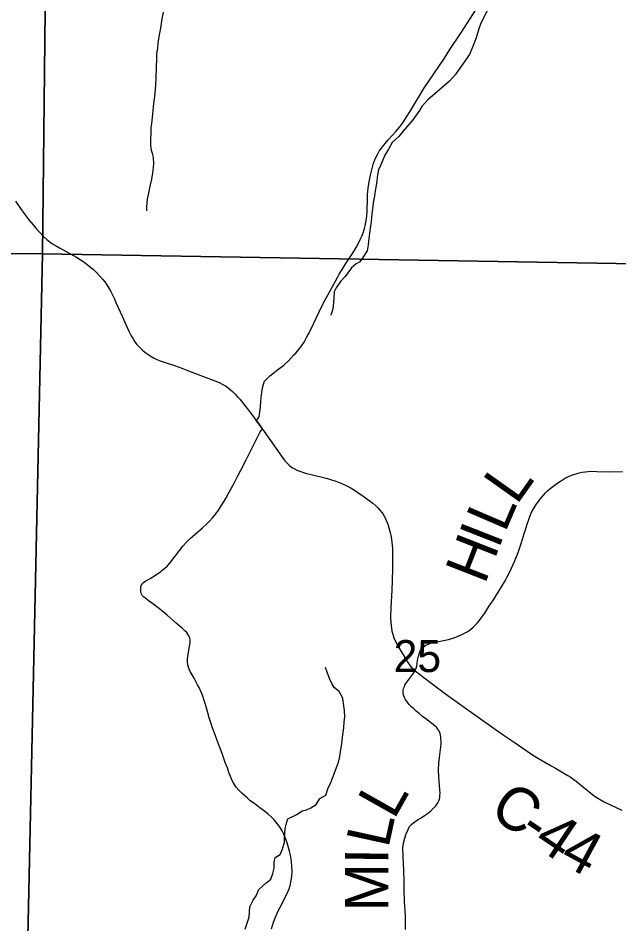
# Model space of a CAD drawing. Extents: x 0 to 34, y 0 to 22.
# Drawn here: x 4.496 to 5.283, y 15.062 to 16.248 of the extents above; entities that cross this region are included whole.
import ezdxf

# ---------------------------------------------------------------- set-up
doc = ezdxf.new("R2010")
doc.units = 0
for name, color, linetype in [('GM_X_Corporation', 7, 'Continuous'), ('GM_X_County_Road_Text', 7, 'Continuous'), ('GM_X_Interstate_Route', 7, 'Continuous'), ('GM_X_Major_Lake', 7, 'Continuous'), ('GM_X_Minor_Lake', 7, 'Continuous'), ('GM_X_Section', 7, 'Continuous'), ('GM_X_Township_Road_Text', 7, 'Continuous')]:
    doc.layers.add(name, color=color, linetype=linetype)

msp = doc.modelspace()

# ---------------------------------------------------------------- linework, layer by layer
at = {"layer": 'GM_X_Corporation'}
for points in [[(4.4923, 16.0084), (4.4987, 15.999), (4.5044, 15.9912), (4.51, 15.984), (4.5153, 15.9775), (4.519, 15.973), (4.524, 15.9676), (4.5287, 15.9628), (4.5335, 15.9585), (4.5379, 15.9549), (4.5409, 15.9526), (4.5446, 15.9503), (4.5498, 15.9473), (4.5721, 15.9351), (4.577, 15.9322), (4.5817, 15.9291), (4.5864, 15.9257), (4.5912, 15.9218), (4.5945, 15.9188), (4.5984, 15.9149), (4.603, 15.9103), (4.6067, 15.9061), (4.6092, 15.9029), (4.612, 15.8989), (4.6147, 15.8946), (4.6166, 15.891), (4.6216, 15.8815), (4.624, 15.876), (4.6322, 15.8578), (4.6352, 15.8509), (4.6407, 15.8383), (4.644, 15.832), (4.6463, 15.8282), (4.6488, 15.8242), (4.6515, 15.8208), (4.6544, 15.8176), (4.6582, 15.8138), (4.662, 15.8108), (4.6656, 15.808), (4.6689, 15.8058), (4.6731, 15.8034), (4.6776, 15.8013), (4.6818, 15.7996), (4.6883, 15.7974), (4.6979, 15.7942), (4.7081, 15.7908), (4.719, 15.7865), (4.7537, 15.7733), (4.7591, 15.771), (4.7633, 15.7689), (4.7675, 15.7665), (4.7712, 15.7639), (4.7736, 15.762), (4.7767, 15.7593), (4.7803, 15.7558), (4.7834, 15.7525), (4.7863, 15.7492), (4.7976, 15.735), (4.8042, 15.7262), (4.8069, 15.7227), (4.8078, 15.7215)], [(4.8078, 15.7215), (4.8111, 15.7171), (4.8162, 15.7102)], [(4.8162, 15.7102), (4.8184, 15.7071), (4.8432, 15.6714), (4.8456, 15.6682), (4.8487, 15.665), (4.8511, 15.6627), (4.8546, 15.6599), (4.858, 15.658), (4.8609, 15.6565), (4.8648, 15.6549), (4.8699, 15.6532), (4.8724, 15.6524), (4.8941, 15.647), (4.9012, 15.6452), (4.9065, 15.6438), (4.912, 15.642), (4.9166, 15.6403), (4.921, 15.6384), (4.9258, 15.6361), (4.931, 15.6334), (4.9364, 15.63), (4.9408, 15.6272), (4.9491, 15.6212), (4.9558, 15.6164), (4.9605, 15.613), (4.9643, 15.6098), (4.9671, 15.6071), (4.9698, 15.604), (4.9726, 15.6004), (4.975, 15.597), (4.9769, 15.5937), (4.9785, 15.5897), (4.9801, 15.5857), (4.9816, 15.5807), (4.9832, 15.5748), (4.9844, 15.5687), (4.9853, 15.5626), (4.9862, 15.5532), (4.9864, 15.5378), (4.9863, 15.5278), (4.986, 15.5113), (4.9855, 15.4992), (4.9843, 15.4764), (4.9839, 15.4635), (4.984, 15.4573), (4.9844, 15.4526), (4.9849, 15.4493), (4.9857, 15.4454), (4.9867, 15.4414), (4.9883, 15.4369), (4.9907, 15.4313), (4.994, 15.4253), (4.9977, 15.4188), (5.001, 15.4131), (5.0057, 15.4056), (5.0088, 15.4014), (5.0109, 15.3986), (5.0137, 15.396), (5.0162, 15.3937), (5.0178, 15.3923), (5.0199, 15.3905), (5.0436, 15.3727), (5.0559, 15.3636), (5.0895, 15.3393), (5.1164, 15.3202), (5.1316, 15.3097), (5.1459, 15.3), (5.1686, 15.2846), (5.1753, 15.2803), (5.186, 15.274), (5.1944, 15.2692), (5.1998, 15.2661), (5.2044, 15.2635), (5.211, 15.2596), (5.2161, 15.2567), (5.2193, 15.2547), (5.2271, 15.2491), (5.2298, 15.247), (5.2373, 15.2408), (5.2435, 15.2357), (5.2484, 15.2318), (5.2519, 15.2292), (5.2556, 15.2268), (5.2637, 15.222), (5.2662, 15.2207), (5.2868, 15.2112)]]:
    msp.add_lwpolyline(points, dxfattribs=at)
at = {"layer": 'GM_X_Interstate_Route'}
for points in [[(4.877, 15.8361), (4.8784, 15.8387), (4.8829, 15.8478), (4.8904, 15.8637), (4.8965, 15.8764), (4.902, 15.8863), (4.9141, 15.9085), (4.9166, 15.9129), (4.9224, 15.9225), (4.9253, 15.927), (4.9297, 15.9336), (4.9357, 15.9425), (4.9389, 15.9479), (4.9419, 15.9534), (4.9442, 15.9582), (4.9462, 15.9628), (4.9479, 15.967), (4.9497, 15.9727), (4.9506, 15.9762), (4.9516, 15.9809), (4.9523, 15.9852), (4.9528, 15.9899), (4.9531, 15.9953), (4.9534, 16.0124), (4.9537, 16.017), (4.9545, 16.0253), (4.9558, 16.034), (4.9575, 16.0426), (4.9587, 16.0479), (4.9601, 16.0531), (4.9616, 16.0581), (4.9633, 16.0626), (4.9646, 16.0656), (4.9666, 16.0694), (4.9691, 16.0739), (4.9732, 16.0795), (4.9767, 16.0838), (4.9808, 16.0889), (4.9907, 16.0998), (4.9959, 16.106), (4.9985, 16.1093), (5.0008, 16.1124), (5.0044, 16.118), (5.0098, 16.1268), (5.0168, 16.1386), (5.0216, 16.1463), (5.0249, 16.1518), (5.0275, 16.1558), (5.0544, 16.1958), (5.0617, 16.2071), (5.0757, 16.2286), (5.1129, 16.2866)], [(4.8078, 15.7215), (4.8099, 15.7237), (4.8106, 15.7248), (4.8116, 15.7269), (4.8121, 15.7289), (4.8127, 15.7326), (4.8132, 15.7387), (4.8139, 15.7465), (4.8144, 15.751), (4.8151, 15.758), (4.8159, 15.764), (4.8171, 15.7691), (4.8188, 15.7727), (4.8209, 15.7752), (4.8229, 15.7771), (4.8256, 15.7797), (4.8292, 15.7826), (4.8355, 15.7875), (4.8438, 15.7939), (4.8501, 15.7995), (4.8572, 15.8071), (4.8596, 15.8096), (4.8614, 15.8117), (4.8649, 15.8161), (4.8675, 15.8195), (4.8704, 15.8241), (4.873, 15.8282), (4.8743, 15.8308), (4.877, 15.8361)], [(4.8162, 15.7102), (4.8111, 15.7171), (4.8078, 15.7215)], [(4.828, 15.0559), (4.8306, 15.0646), (4.8325, 15.0701), (4.8342, 15.0742), (4.8362, 15.0785), (4.8385, 15.0832), (4.8479, 15.101), (4.8508, 15.108), (4.8523, 15.1126), (4.8533, 15.1171), (4.8541, 15.1212), (4.8545, 15.1253), (4.8547, 15.1305), (4.8545, 15.1382), (4.8541, 15.1425), (4.8534, 15.148), (4.8523, 15.1539), (4.8515, 15.1573), (4.8483, 15.1683), (4.8472, 15.1718), (4.8454, 15.1767), (4.844, 15.1799), (4.8417, 15.1841), (4.8391, 15.1883), (4.8363, 15.1925), (4.834, 15.1954), (4.831, 15.1988), (4.8281, 15.2017), (4.8235, 15.2058), (4.8186, 15.2098), (4.8127, 15.2144), (4.8058, 15.2194), (4.7999, 15.2236), (4.7958, 15.2272), (4.7923, 15.2303), (4.7891, 15.2334), (4.785, 15.2375), (4.7816, 15.2414), (4.7792, 15.245), (4.7771, 15.2484), (4.7753, 15.2522), (4.772, 15.2607), (4.77, 15.2665), (4.7672, 15.2735), (4.7637, 15.2839), (4.7605, 15.2922), (4.7584, 15.2977), (4.7539, 15.3098), (4.7511, 15.3178), (4.7489, 15.3243), (4.7463, 15.3322), (4.7439, 15.3403), (4.7412, 15.3494), (4.7395, 15.3549), (4.7372, 15.3619), (4.7362, 15.3646), (4.7328, 15.3719), (4.731, 15.3753), (4.7264, 15.3839), (4.7237, 15.3883), (4.7211, 15.3928), (4.7189, 15.3982), (4.718, 15.4016), (4.7177, 15.4052), (4.7179, 15.4095), (4.7185, 15.4155), (4.7199, 15.423), (4.7208, 15.4284), (4.7211, 15.4305), (4.721, 15.4347), (4.7208, 15.4362), (4.7201, 15.4384), (4.7192, 15.4401), (4.7181, 15.4418), (4.7164, 15.444), (4.7143, 15.4461), (4.7107, 15.4494), (4.703, 15.456), (4.6909, 15.4664), (4.6811, 15.4746), (4.6724, 15.4812), (4.6661, 15.4857), (4.6629, 15.4883), (4.6601, 15.4905), (4.6588, 15.492), (4.6577, 15.4936), (4.657, 15.4953), (4.6567, 15.497), (4.6564, 15.4994), (4.6565, 15.5016), (4.6567, 15.5031), (4.6572, 15.5052), (4.6582, 15.5072), (4.6594, 15.5086), (4.6612, 15.51), (4.6632, 15.5113), (4.6658, 15.5129), (4.6688, 15.5144), (4.676, 15.5187), (4.6826, 15.5236), (4.6847, 15.5252), (4.6877, 15.5277), (4.691, 15.5308), (4.6941, 15.5341), (4.6974, 15.5381), (4.7115, 15.5569), (4.7163, 15.5619), (4.7218, 15.5673), (4.7273, 15.5721), (4.7375, 15.5808), (4.743, 15.5861), (4.7466, 15.5896), (4.7505, 15.5938), (4.7536, 15.5976), (4.7582, 15.6039), (4.7659, 15.6156), (4.7686, 15.62), (4.7725, 15.6273), (4.7792, 15.6401), (4.7835, 15.6487), (4.7874, 15.6562), (4.7944, 15.6697), (4.8069, 15.6943), (4.8103, 15.7014), (4.8125, 15.7055), (4.8144, 15.7081), (4.8162, 15.7102)], [(5.0162, 15.3937), (5.0167, 15.3948), (5.0175, 15.3969), (5.0183, 15.3997), (5.0188, 15.4031), (5.0193, 15.4076), (5.0204, 15.413), (5.0212, 15.416), (5.022, 15.4181), (5.0232, 15.4206), (5.025, 15.4228), (5.0262, 15.4242), (5.0282, 15.4259), (5.03, 15.427), (5.0323, 15.4282), (5.0353, 15.4294), (5.0392, 15.4305), (5.0449, 15.4316), (5.0532, 15.4332), (5.0598, 15.4348), (5.0653, 15.4363), (5.0692, 15.4377), (5.0763, 15.4407), (5.0806, 15.4428), (5.0849, 15.4453), (5.0884, 15.4477), (5.092, 15.4506), (5.0944, 15.4528), (5.0974, 15.4561), (5.1002, 15.4595), (5.1032, 15.4634), (5.1073, 15.4693), (5.1127, 15.4778), (5.1185, 15.4867), (5.1293, 15.5037), (5.134, 15.5115), (5.1364, 15.516), (5.1395, 15.5223), (5.1463, 15.5368), (5.1481, 15.5412), (5.1509, 15.5484), (5.1532, 15.5552), (5.1552, 15.5615), (5.1592, 15.5747), (5.16, 15.577), (5.1627, 15.5856), (5.1649, 15.5918), (5.1664, 15.5958), (5.1682, 15.6), (5.1691, 15.6021), (5.1718, 15.6071), (5.1731, 15.6091), (5.1754, 15.6125), (5.1777, 15.6155), (5.1796, 15.6181), (5.1845, 15.6238), (5.187, 15.6266), (5.1895, 15.6291), (5.1926, 15.632), (5.1964, 15.6351), (5.2015, 15.6388), (5.2063, 15.6419), (5.2118, 15.6452), (5.2171, 15.6479), (5.2223, 15.6501), (5.2269, 15.6517), (5.2308, 15.6528), (5.2348, 15.6537), (5.2389, 15.6543), (5.2429, 15.6547), (5.2468, 15.6549), (5.2541, 15.6547), (5.2695, 15.6542), (5.2879, 15.6547)], [(5.0034, 15.0551), (5.0032, 15.0718), (5.0028, 15.0796), (5.0024, 15.0854), (5.0019, 15.0922), (5.0017, 15.1069), (5.0015, 15.1174), (5.0011, 15.132), (5.0002, 15.1503), (5.0001, 15.1618), (5.0008, 15.168), (5.0024, 15.1746), (5.0042, 15.1803), (5.0068, 15.186), (5.0088, 15.1897), (5.0111, 15.1923), (5.0142, 15.1951), (5.0177, 15.1975), (5.0201, 15.199), (5.0239, 15.2013), (5.0285, 15.2043), (5.0334, 15.2078), (5.0364, 15.2103), (5.0394, 15.2129), (5.0431, 15.217), (5.0458, 15.2206), (5.0471, 15.2233), (5.0479, 15.2255), (5.0482, 15.2278), (5.0485, 15.2303), (5.0487, 15.2336), (5.0486, 15.2376), (5.0472, 15.2548), (5.0468, 15.2641), (5.047, 15.2728), (5.048, 15.2803), (5.049, 15.2872), (5.0499, 15.2942), (5.0502, 15.2983), (5.0498, 15.3074), (5.0488, 15.3115), (5.0471, 15.3154), (5.0459, 15.3174), (5.0439, 15.3197), (5.0418, 15.3216), (5.0379, 15.3248), (5.0301, 15.3309), (5.0258, 15.334), (5.0214, 15.3376), (5.0175, 15.3407), (5.0142, 15.3437), (5.0113, 15.3464), (5.0082, 15.3496), (5.0054, 15.353), (5.0033, 15.3559), (5.0019, 15.3585), (5.001, 15.361), (5.0005, 15.3638), (5.0004, 15.366), (5.0005, 15.3686), (5.0009, 15.3706), (5.0019, 15.3733), (5.0026, 15.3748), (5.004, 15.3771), (5.0063, 15.3804), (5.0118, 15.3874), (5.0142, 15.3909), (5.0162, 15.3937)]]:
    msp.add_lwpolyline(points, dxfattribs=at)
at = {"layer": 'GM_X_Minor_Lake'}
for points in [[(3.7042, 16.9849), (4.539, 16.9739), (4.5275, 15.9394), (3.6897, 15.9465), (3.703, 16.8594)], [(4.539, 16.9739), (5.5566, 16.9477), (5.5393, 15.9226), (4.5275, 15.9394)], [(4.5275, 15.9394), (4.5059, 14.9222), (3.6743, 14.926), (3.688, 15.8589), (3.6897, 15.9465)], [(5.5393, 15.9226), (5.5097, 14.9125), (4.5059, 14.9222), (4.5275, 15.9394)]]:
    msp.add_lwpolyline(points, close=True, dxfattribs=at)
at = {"layer": 'GM_X_Township_Road_Text'}
for points in [[(5.1131, 16.2631), (5.1021, 16.2413), (5.0992, 16.2329), (5.0959, 16.2225), (5.0912, 16.2099), (5.0872, 16.2007), (5.0738, 16.1815), (5.0686, 16.1738), (5.0612, 16.1657), (5.0485, 16.1548), (5.0328, 16.1413), (5.0249, 16.1324), (5.0216, 16.127), (5.0131, 16.1151), (5, 16.0997), (4.9945, 16.0931), (4.9859, 16.0854), (4.9811, 16.0766), (4.9763, 16.0689), (4.9711, 16.0559), (4.9682, 16.0497), (4.9668, 16.0429), (4.9654, 16.0318), (4.9637, 16.0219), (4.9627, 16.015), (4.9616, 16.0093), (4.9602, 15.9986), (4.9589, 15.9875), (4.9582, 15.9814), (4.9575, 15.9761), (4.9562, 15.9666), (4.9555, 15.9597), (4.9545, 15.9513), (4.9531, 15.9433), (4.9475, 15.9348), (4.9435, 15.9291), (4.9386, 15.9263), (4.9326, 15.9213), (4.9278, 15.9148), (4.9244, 15.9098), (4.9181, 15.9032), (4.9125, 15.8951), (4.91, 15.8898), (4.9093, 15.8821), (4.9087, 15.8707), (4.9077, 15.8657), (4.9062, 15.8604), (4.9053, 15.8586)], [(4.6858, 16.256), (4.684, 16.2472), (4.6823, 16.235), (4.6809, 16.2285), (4.6799, 16.2209), (4.6788, 16.2152), (4.6782, 16.2091), (4.6771, 16.2011), (4.6769, 16.1931), (4.6766, 16.1858), (4.6767, 16.1794), (4.6764, 16.1733), (4.6761, 16.1683), (4.6755, 16.1546), (4.6745, 16.1455), (4.6732, 16.1363), (4.6725, 16.1268), (4.6715, 16.1184), (4.6705, 16.1096), (4.6698, 16.1047), (4.6696, 16.0974), (4.6693, 16.0898), (4.6694, 16.0814)], [(4.6694, 16.0814), (4.6703, 16.0754), (4.6718, 16.0701), (4.6727, 16.0647), (4.6732, 16.0579), (4.6729, 16.0526), (4.6718, 16.0457), (4.6704, 16.0373), (4.6686, 16.0297), (4.6669, 16.0216), (4.6662, 16.0167), (4.6648, 16.0109), (4.6638, 16.001), (4.6638, 15.9957)], [(4.8737, 15.2117), (4.8793, 15.2141), (4.8864, 15.2184), (4.8912, 15.2264), (4.8991, 15.2307), (4.9016, 15.2391), (4.9057, 15.2476), (4.9097, 15.2587), (4.9155, 15.274), (4.9173, 15.2816), (4.9187, 15.2904), (4.9201, 15.298), (4.9207, 15.3068), (4.9228, 15.319), (4.9231, 15.327), (4.9241, 15.3335), (4.9236, 15.3415), (4.922, 15.351), (4.9211, 15.3578), (4.9164, 15.3665), (4.9103, 15.3714), (4.9068, 15.377), (4.9037, 15.3834), (4.9009, 15.3918), (4.8985, 15.3979)], [(4.7934, 15.0552), (4.7985, 15.0713), (4.7994, 15.0846), (4.8038, 15.0935), (4.8075, 15.0992), (4.8112, 15.1073), (4.8205, 15.1154), (4.8269, 15.1208), (4.8294, 15.1281), (4.8312, 15.1353), (4.8315, 15.143), (4.8325, 15.1491), (4.8393, 15.153), (4.8419, 15.1591), (4.8448, 15.1687), (4.8447, 15.1755), (4.8456, 15.1866), (4.847, 15.193), (4.8492, 15.1999), (4.8609, 15.2054), (4.868, 15.2101), (4.8737, 15.2117)]]:
    msp.add_lwpolyline(points, dxfattribs=at)

# ---------------------------------------------------------------- texts
at = {"layer": 'GM_X_County_Road_Text'}
msp.add_text('25', height=0.04186, rotation=0, dxfattribs=at).set_placement((4.9878, 15.392))
at = {"layer": 'GM_X_Major_Lake'}
for s, rotation, p in [('C', 325.8163, (5.1111, 15.2052)), ('-', 325.8702, (5.1497, 15.179)), ('4', 326.0756, (5.1692, 15.1658)), ('4', 331.4263, (5.2032, 15.1432))]:
    msp.add_text(s, height=0.0568, rotation=rotation, dxfattribs=at).set_placement(p)
at = {"layer": 'GM_X_Section'}
for s, rotation, p in [('L', 54.7134, (5.149, 15.6097)), ('L', 66.766, (5.1338, 15.5734)), ('I', 68.5421, (5.1254, 15.5521)), ('H', 68.6471, (5.1072, 15.5056)), ('L', 60.6394, (4.9883, 15.1977)), ('L', 77.626, (4.9808, 15.1603)), ('I', 89.1647, (4.9808, 15.14)), ('M', 89.9675, (4.9808, 15.0786))]:
    msp.add_text(s, height=0.0568, rotation=rotation, dxfattribs=at).set_placement(p)

doc.saveas('drawing.dxf')
